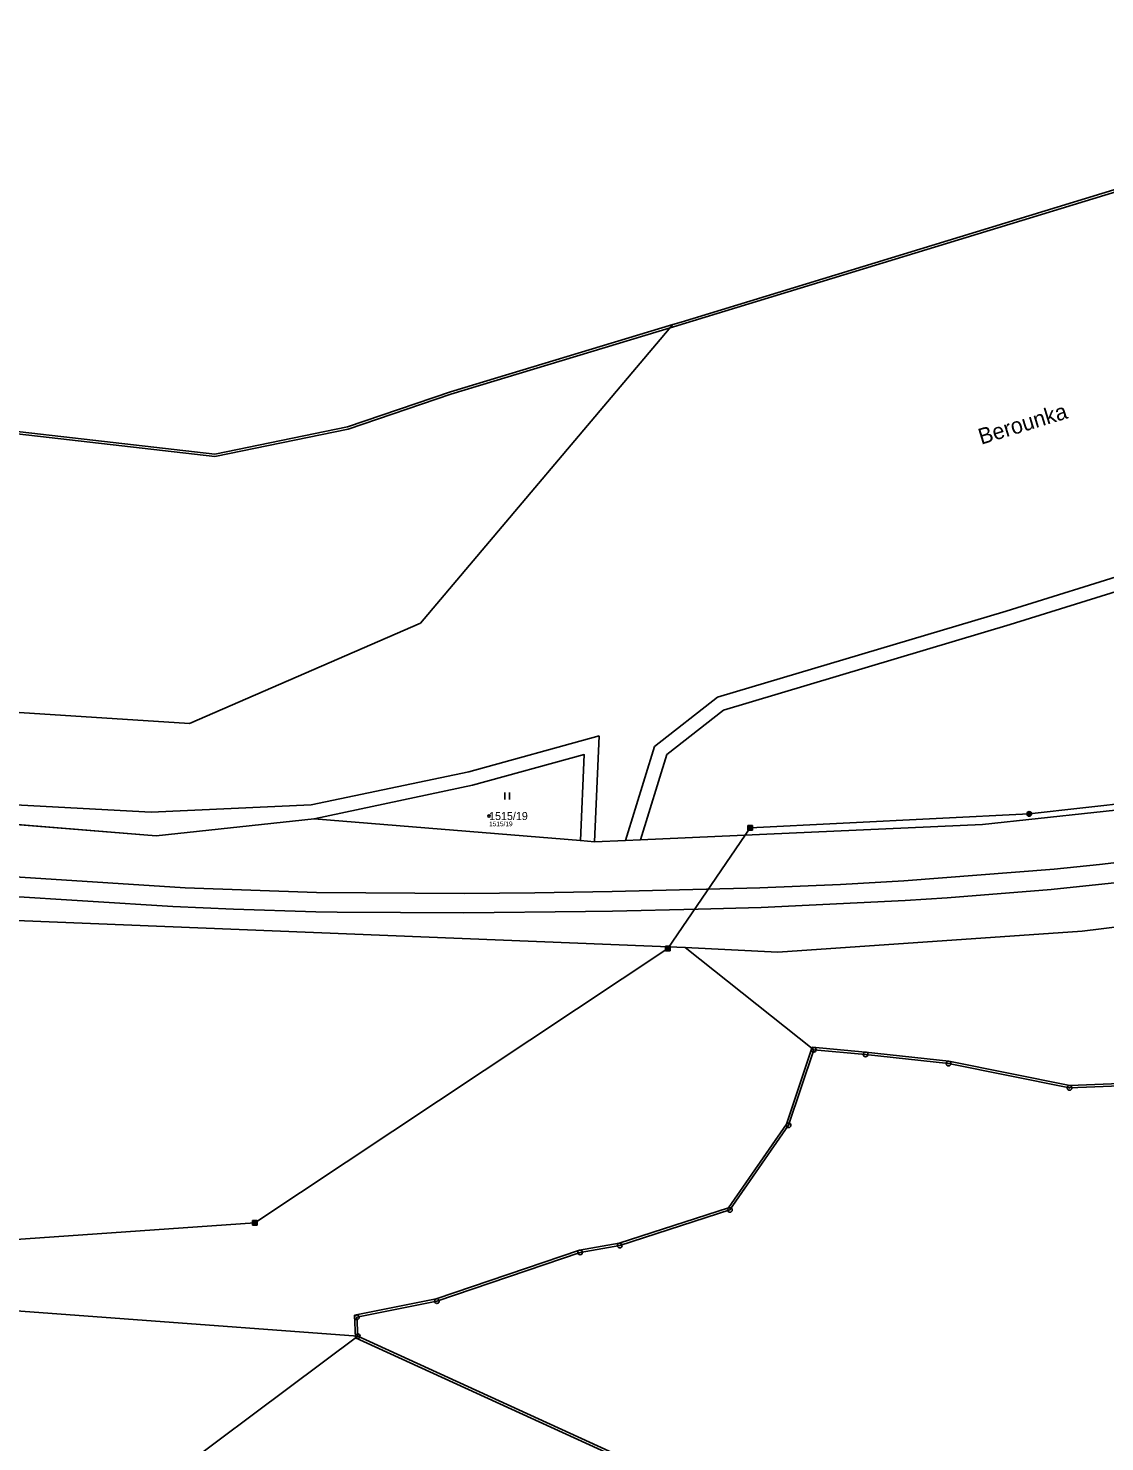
# Model space of a CAD drawing. Extents: x -770088 to -765625, y -1057899 to -1053934.
# Drawn here: x -767179.8 to -766951, y -1055092.4 to -1054792.1 of the extents above; entities that cross this region are included whole.
import ezdxf

# ---------------------------------------------------------------- set-up
doc = ezdxf.new("R2010")
doc.units = 0
for name, color, linetype in [('Definiční body', 7, 'Continuous'), ('Hranice parcel', 7, 'Continuous'), ('Parcelní čísla', 7, 'Continuous'), ('Polygon ku', 7, 'Continuous'), ('Polygon parcely', 7, 'Continuous'), ('Pop  PČ popisy', 7, 'Continuous'), ('Poz předměty', 7, 'Continuous'), ('Vnitřní kresba', 7, 'Continuous'), ('Značky bodu BP', 7, 'Continuous'), ('Značky kultur', 7, 'Continuous')]:
    doc.layers.add(name, color=color, linetype=linetype)

msp = doc.modelspace()

# ---------------------------------------------------------------- linework, layer by layer
at = {"layer": 'Definiční body'}
msp.add_circle((-767081.88, -1054959.47), 0.25, dxfattribs=at)
at = {"layer": 'Hranice parcel'}
for p, q in [((-767090.1, -1054869.34), (-767042.8, -1054855.07)), ((-767041.07, -1054854.55), (-767042.8, -1054855.07)), ((-767111.97, -1054876.78), (-767090.1, -1054869.34)), ((-767152.63, -1054963.64), (-767235.16, -1054957.04)), ((-767119.07, -1054960.05), (-767152.63, -1054963.64)), ((-767062.46, -1054964.69), (-767119.07, -1054960.05)), ((-767059.47, -1054964.94), (-767062.46, -1054964.69)), ((-767012.88, -1055009.13), (-767040.18, -1054987.39))]:
    msp.add_line(p, q, dxfattribs=at)
for points in [[(-767042.8, -1054855.07), (-767096.48, -1054918.48), (-767145.53, -1054939.79), (-767199.4, -1054936.37), (-767218.08, -1054938.78), (-767304.22, -1054935.91), (-767317.34, -1054929.04), (-767334.65, -1054909.7), (-767354.59, -1054874.29), (-767364.17, -1054843.9), (-767376.37, -1054815.85), (-767392.88, -1054792.13)], [(-767041.07, -1054854.55), (-766931.02, -1054820.95), (-766894.55, -1054809.81)], [(-767260.21, -1054864.01), (-767211.84, -1054874.41), (-767140.17, -1054882.61), (-767111.97, -1054876.78)], [(-767049.72, -1054964.55), (-767044.08, -1054946.42), (-767032.09, -1054937.01), (-766971.16, -1054918.81), (-766921.73, -1054903.41), (-766847.75, -1054883.2)], [(-766578.31, -1054919.97), (-766662.58, -1054923.34), (-766747.52, -1054931.18), (-766836.88, -1054944.91), (-766894.23, -1054952.33), (-766977.01, -1054961.27), (-767049.72, -1054964.55)], [(-767040.18, -1054987.39), (-767182.41, -1054981.69), (-767267.36, -1054975.85), (-767344.04, -1054968.14), (-767346.77, -1054973.36), (-767372.36, -1054980.44), (-767381.09, -1054971.25), (-767376.02, -1054961.44), (-767462.61, -1054944.07), (-767479.62, -1054945.09), (-767514.25, -1054935.59)], [(-767119.07, -1054960.05), (-767085.39, -1054952.94), (-767061.66, -1054946.42), (-767062.46, -1054964.69)], [(-767549.86, -1054975.62), (-767508.25, -1054990.79), (-767472.4, -1054967.24), (-767447.46, -1054960.98), (-767423.39, -1054971.25), (-767398.03, -1055002.58), (-767368.4, -1055013.68), (-767367.33, -1054994.3), (-767343.15, -1054986.96), (-767306.46, -1055021.07), (-767217.76, -1055015.77), (-767308.49, -1055055.25), (-767109.8, -1055069.97)], [(-767049.72, -1054964.55), (-767052.91, -1054964.69), (-767059.47, -1054964.94)], [(-766560.42, -1054967.72), (-766581.98, -1054974.42), (-766596.86, -1054975.69), (-766611.1, -1054978.92), (-766635.67, -1054983.77), (-766660.92, -1054987.33), (-766680.18, -1054987.49), (-766692.25, -1054983.78), (-766734.01, -1054981.03), (-766754.08, -1054989.45), (-766770.43, -1054996.73), (-766801.51, -1055003.69), (-766834.6, -1055009.98), (-766865.19, -1055012.57), (-766915.53, -1055015.48), (-766958.5, -1055017.22), (-766984.24, -1055012.04), (-767001.88, -1055010.1), (-767012.88, -1055009.13)], [(-766838.73, -1054976.16), (-766846.04, -1054976.95), (-766846.54, -1054971.38), (-766855.03, -1054971.56), (-766955.82, -1054983.96), (-767020.55, -1054988.36), (-767040.18, -1054987.39)], [(-767012.88, -1055009.13), (-767018.23, -1055025.16), (-767030.69, -1055043.13), (-767054.12, -1055050.7), (-767062.54, -1055052.16), (-767092.97, -1055062.52), (-767109.96, -1055065.92), (-767109.8, -1055069.97)], [(-767109.8, -1055069.97), (-767213.73, -1055147.54), (-767202.65, -1055164.21), (-767185.2, -1055166.93), (-767184.14, -1055193.9), (-767186.41, -1055239.36), (-767216.46, -1055248.45), (-767230.58, -1055260.73), (-767237.87, -1055279.82), (-767248.19, -1055299.21), (-767260.48, -1055298.76), (-767280.97, -1055281.94), (-767279.45, -1055266.94), (-767282.79, -1055257.85), (-767284.92, -1055235.27), (-767297.29, -1055228.82), (-767286.22, -1055218.43), (-767281.3, -1055204.36), (-767298.69, -1055184.62)], [(-767109.8, -1055069.97), (-767041.33, -1055101.22), (-767014.03, -1055116.71), (-766992.99, -1055123.51)]]:
    msp.add_lwpolyline(points, dxfattribs=at)
at = {"layer": 'Polygon ku'}
msp.add_lwpolyline([(-766931.02, -1054820.95), (-767041.07, -1054854.55), (-767042.8, -1054855.07), (-767090.1, -1054869.34), (-767111.97, -1054876.78), (-767140.17, -1054882.61), (-767211.84, -1054874.41)], dxfattribs=at)
at = {"layer": 'Polygon parcely'}
for points in [[(-767392.88, -1054792.13), (-767376.37, -1054815.85), (-767364.17, -1054843.9), (-767354.59, -1054874.29), (-767334.65, -1054909.7), (-767317.34, -1054929.04), (-767304.22, -1054935.91), (-767218.08, -1054938.78), (-767199.4, -1054936.37), (-767145.53, -1054939.79), (-767096.48, -1054918.48), (-767042.8, -1054855.07), (-767090.1, -1054869.34), (-767111.97, -1054876.78), (-767140.17, -1054882.61), (-767211.84, -1054874.41), (-767260.21, -1054864.01), (-767283.35, -1054855.99), (-767313.16, -1054845.16), (-767345.05, -1054830.51), (-767357.9, -1054823.47), (-767385.74, -1054799)], [(-767062.46, -1054964.69), (-767061.66, -1054946.42), (-767085.39, -1054952.94), (-767119.07, -1054960.05)]]:
    msp.add_lwpolyline(points, close=True, dxfattribs=at)
for points in [[(-766931.02, -1054820.95), (-767041.07, -1054854.55), (-767042.8, -1054855.07), (-767096.48, -1054918.48), (-767145.53, -1054939.79), (-767199.4, -1054936.37)], [(-767235.16, -1054957.04), (-767152.63, -1054963.64), (-767119.07, -1054960.05), (-767085.39, -1054952.94), (-767061.66, -1054946.42), (-767062.46, -1054964.69), (-767059.47, -1054964.94), (-767052.91, -1054964.69), (-767049.72, -1054964.55), (-767044.08, -1054946.42), (-767032.09, -1054937.01), (-766971.16, -1054918.81), (-766921.73, -1054903.41), (-766847.75, -1054883.2), (-766763.3, -1054858.51), (-766744.81, -1054852.9), (-766703.76, -1054844.77)], [(-766703.76, -1054844.77), (-766744.81, -1054852.9), (-766763.3, -1054858.51), (-766847.75, -1054883.2), (-766921.73, -1054903.41), (-766971.16, -1054918.81), (-767032.09, -1054937.01), (-767044.08, -1054946.42), (-767049.72, -1054964.55), (-766977.01, -1054961.27), (-766894.23, -1054952.33), (-766836.88, -1054944.91), (-766747.52, -1054931.18), (-766662.58, -1054923.34)], [(-766355.68, -1054945.89), (-766357.52, -1054953.03), (-766377.61, -1054951.4), (-766412.09, -1054948.97), (-766441.48, -1054947.01), (-766471.64, -1054932.14), (-766477.88, -1054929.07), (-766527.45, -1054920.92), (-766564.09, -1054919.66), (-766578.31, -1054919.97), (-766662.58, -1054923.34), (-766747.52, -1054931.18), (-766836.88, -1054944.91), (-766894.23, -1054952.33), (-766977.01, -1054961.27), (-767049.72, -1054964.55), (-767052.91, -1054964.69), (-767059.47, -1054964.94), (-767062.46, -1054964.69), (-767119.07, -1054960.05), (-767152.63, -1054963.64), (-767235.16, -1054957.04)], [(-767182.41, -1054981.69), (-767040.18, -1054987.39), (-767020.55, -1054988.36), (-766955.82, -1054983.96), (-766855.03, -1054971.56), (-766846.54, -1054971.38), (-766846.04, -1054976.95), (-766838.73, -1054976.16), (-766820.52, -1054973.73), (-766814.82, -1054972.91), (-766815.76, -1054965.97), (-766783.67, -1054959.65), (-766727.95, -1054957.74), (-766584.45, -1054947.2)], [(-766855.03, -1054971.56), (-766955.82, -1054983.96), (-767020.55, -1054988.36), (-767040.18, -1054987.39), (-767012.88, -1055009.13), (-767001.88, -1055010.1), (-766984.24, -1055012.04), (-766958.5, -1055017.22), (-766915.53, -1055015.48)], [(-767308.49, -1055055.25), (-767109.8, -1055069.97), (-767109.96, -1055065.92), (-767092.97, -1055062.52), (-767062.54, -1055052.16), (-767054.12, -1055050.7), (-767030.69, -1055043.13), (-767018.23, -1055025.16), (-767012.88, -1055009.13), (-767040.18, -1054987.39), (-767182.41, -1054981.69)], [(-766692.25, -1054983.78), (-766734.01, -1054981.03), (-766754.08, -1054989.45), (-766770.43, -1054996.73), (-766801.51, -1055003.69), (-766834.6, -1055009.98), (-766865.19, -1055012.57), (-766915.53, -1055015.48), (-766958.5, -1055017.22), (-766984.24, -1055012.04), (-767001.88, -1055010.1), (-767012.88, -1055009.13), (-767018.23, -1055025.16), (-767030.69, -1055043.13), (-767054.12, -1055050.7), (-767062.54, -1055052.16), (-767092.97, -1055062.52), (-767109.96, -1055065.92), (-767109.8, -1055069.97), (-767041.33, -1055101.22)], [(-767213.73, -1055147.54), (-767109.8, -1055069.97), (-767308.49, -1055055.25)], [(-767041.33, -1055101.22), (-767109.8, -1055069.97), (-767213.73, -1055147.54), (-767202.65, -1055164.21), (-767185.2, -1055166.93)]]:
    msp.add_lwpolyline(points, dxfattribs=at)
at = {"layer": 'Poz předměty'}
for p, q in [((-766967.09, -1054959.02), (-766909.43, -1054952.53)), ((-767026.37, -1054961.97), (-766967.09, -1054959.02)), ((-767043.91, -1054987.62), (-767026.37, -1054961.97)), ((-767026.87, -1054961.47), (-767025.87, -1054961.47)), ((-767026.87, -1054962.47), (-767026.87, -1054961.47)), ((-767026.87, -1054961.67), (-767025.87, -1054961.67)), ((-767026.87, -1054961.87), (-767025.87, -1054961.87)), ((-767026.87, -1054962.07), (-767025.87, -1054962.07)), ((-767026.87, -1054962.27), (-767025.87, -1054962.27)), ((-767026.67, -1054962.47), (-767026.67, -1054961.47)), ((-767026.47, -1054962.47), (-767026.47, -1054961.47)), ((-767026.27, -1054962.47), (-767026.27, -1054961.47)), ((-767026.07, -1054962.47), (-767026.07, -1054961.47)), ((-767025.87, -1054962.47), (-767025.87, -1054961.47)), ((-767026.87, -1054962.47), (-767025.87, -1054962.47)), ((-766952.18, -1054969.76), (-766929.91, -1054967.24)), ((-766993.72, -1054973.25), (-766961.81, -1054970.74)), ((-766961.81, -1054970.74), (-766952.18, -1054969.76)), ((-767184.9, -1054972.21), (-767179.38, -1054972.61)), ((-767179.38, -1054972.61), (-767146.47, -1054974.7)), ((-767024.34, -1054974.69), (-767007.21, -1054974)), ((-767007.21, -1054974), (-766993.72, -1054973.25)), ((-766929.4, -1054971.6), (-766962.42, -1054975.04)), ((-767149.09, -1054978.65), (-767185.21, -1054976.39)), ((-767146.47, -1054974.7), (-767118.56, -1054975.69)), ((-767118.56, -1054975.69), (-767087.15, -1054975.9)), ((-767087.15, -1054975.9), (-767072.14, -1054975.77)), ((-767072.14, -1054975.77), (-767055.7, -1054975.52)), ((-767055.7, -1054975.52), (-767027.14, -1054974.78)), ((-767027.14, -1054974.78), (-767024.34, -1054974.69)), ((-766984.56, -1054976.85), (-766993.47, -1054977.44)), ((-766962.42, -1054975.04), (-766984.56, -1054976.85)), ((-767136.18, -1054979.24), (-767149.09, -1054978.65)), ((-767118.73, -1054979.79), (-767136.18, -1054979.24)), ((-767114.16, -1054979.88), (-767118.73, -1054979.79)), ((-767087.24, -1054980.06), (-767114.16, -1054979.88)), ((-767061.41, -1054979.77), (-767087.24, -1054980.06)), ((-767055.66, -1054979.67), (-767061.41, -1054979.77)), ((-767037.46, -1054979.26), (-767055.66, -1054979.67)), ((-767024.07, -1054978.87), (-767037.46, -1054979.26)), ((-766993.47, -1054977.44), (-767024.07, -1054978.87)), ((-767131.67, -1055045.87), (-767043.91, -1054987.62)), ((-767044.41, -1054987.12), (-767043.41, -1054987.12)), ((-767044.41, -1054988.12), (-767044.41, -1054987.12)), ((-767044.41, -1054987.32), (-767043.41, -1054987.32)), ((-767044.41, -1054987.52), (-767043.41, -1054987.52)), ((-767044.41, -1054987.72), (-767043.41, -1054987.72)), ((-767044.41, -1054987.92), (-767043.41, -1054987.92)), ((-767044.41, -1054988.12), (-767043.41, -1054988.12)), ((-767044.21, -1054988.12), (-767044.21, -1054987.12)), ((-767044.01, -1054988.12), (-767044.01, -1054987.12)), ((-767043.81, -1054988.12), (-767043.81, -1054987.12)), ((-767043.61, -1054988.12), (-767043.61, -1054987.12)), ((-767043.41, -1054988.12), (-767043.41, -1054987.12)), ((-767294.52, -1055057.28), (-767131.67, -1055045.87)), ((-767132.17, -1055045.37), (-767131.17, -1055045.37)), ((-767132.17, -1055046.37), (-767132.17, -1055045.37)), ((-767132.17, -1055045.57), (-767131.17, -1055045.57)), ((-767132.17, -1055045.77), (-767131.17, -1055045.77)), ((-767132.17, -1055045.97), (-767131.17, -1055045.97)), ((-767132.17, -1055046.17), (-767131.17, -1055046.17)), ((-767132.17, -1055046.37), (-767131.17, -1055046.37)), ((-767131.97, -1055046.37), (-767131.97, -1055045.37)), ((-767131.77, -1055046.37), (-767131.77, -1055045.37)), ((-767131.57, -1055046.37), (-767131.57, -1055045.37)), ((-767131.37, -1055046.37), (-767131.37, -1055045.37)), ((-767131.17, -1055046.37), (-767131.17, -1055045.37))]:
    msp.add_line(p, q, dxfattribs=at)
for radius in [0.5, 0.4, 0.3, 0.2, 0.1]:
    msp.add_circle((-766967.09, -1054959.02), radius, dxfattribs=at)
at = {"layer": 'Vnitřní kresba'}
for p, q in [((-767042.66, -1054855.55), (-766893.94, -1054810.15)), ((-767090.03, -1054869.84), (-767042.66, -1054855.55)), ((-767111.82, -1054877.26), (-767090.03, -1054869.84)), ((-767211.92, -1054874.9), (-767140.16, -1054883.12)), ((-767140.16, -1054883.12), (-767111.82, -1054877.26)), ((-766972.02, -1054915.94), (-766922.62, -1054900.55)), ((-767033.32, -1054934.25), (-766972.02, -1054915.94)), ((-767046.7, -1054944.73), (-767033.32, -1054934.25)), ((-767058.48, -1054942.44), (-767086.18, -1054950.05)), ((-767059.47, -1054964.94), (-767058.48, -1054942.44)), ((-767046.7, -1054944.73), (-767052.91, -1054964.69)), ((-767119.69, -1054957.11), (-767086.18, -1054950.05)), ((-767234.41, -1054954.29), (-767153.67, -1054958.62)), ((-767119.69, -1054957.11), (-767153.67, -1054958.62)), ((-767018.68, -1055024.93), (-767013.23, -1055008.6)), ((-767013.23, -1055008.6), (-767001.88, -1055009.6)), ((-767001.88, -1055009.6), (-766984.16, -1055011.55)), ((-766984.16, -1055011.55), (-766958.47, -1055016.72)), ((-766958.47, -1055016.72), (-766915.55, -1055014.98)), ((-767031, -1055042.7), (-767018.68, -1055024.93)), ((-767054.23, -1055050.21), (-767031, -1055042.7)), ((-767093.1, -1055062.04), (-767062.65, -1055051.67)), ((-767062.65, -1055051.67), (-767054.23, -1055050.21)), ((-767110.48, -1055065.51), (-767093.1, -1055062.04)), ((-767110.29, -1055070.29), (-767110.48, -1055065.51)), ((-767041.53, -1055101.68), (-767110.29, -1055070.29))]:
    msp.add_line(p, q, dxfattribs=at)
at = {"layer": 'Značky bodu BP'}
for centre, radius in [((-767012.88, -1055009.13), 0.5), ((-767012.88, -1055009.13), 0.0303), ((-767001.88, -1055010.1), 0.5), ((-767001.88, -1055010.1), 0.0303), ((-766984.24, -1055012.04), 0.5), ((-766984.24, -1055012.04), 0.0303), ((-766958.5, -1055017.22), 0.5), ((-766958.5, -1055017.22), 0.0303), ((-767018.23, -1055025.16), 0.5), ((-767018.23, -1055025.16), 0.0303), ((-767030.69, -1055043.13), 0.5), ((-767030.69, -1055043.13), 0.0303), ((-767062.54, -1055052.16), 0.5), ((-767062.54, -1055052.16), 0.0303), ((-767054.12, -1055050.7), 0.5), ((-767054.12, -1055050.7), 0.0303), ((-767092.97, -1055062.52), 0.5), ((-767092.97, -1055062.52), 0.0303), ((-767109.96, -1055065.92), 0.5), ((-767109.96, -1055065.92), 0.0303), ((-767109.8, -1055069.97), 0.5), ((-767109.8, -1055069.97), 0.0303)]:
    msp.add_circle(centre, radius, dxfattribs=at)
at = {"layer": 'Značky kultur'}
for p, q in [((-767078.54, -1054955.94), (-767078.54, -1054954.44)), ((-767077.54, -1054955.94), (-767077.54, -1054954.44))]:
    msp.add_line(p, q, dxfattribs=at)

# ---------------------------------------------------------------- texts
at = {"layer": 'Definiční body'}
msp.add_text('1515/19', height=1, dxfattribs=at).set_placement((-767081.88, -1054961.63))
at = {"layer": 'Parcelní čísla'}
msp.add_text('1515/19', height=1.7, dxfattribs=at).set_placement((-767081.88, -1054960.32))
at = {"layer": 'Pop  PČ popisy'}
msp.add_text('Berounka', height=3.4, rotation=17, dxfattribs=at).set_placement((-766977.3, -1054880.61))

doc.saveas('drawing.dxf')
